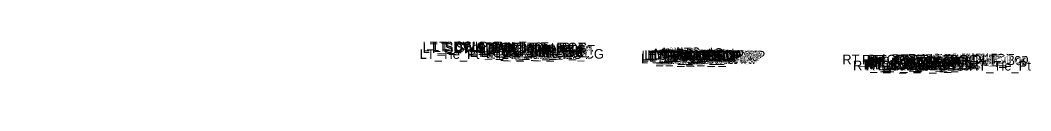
# Model space of a CAD drawing. Extents: x 0 to 4229, y -1 to 9523.
# Drawn here: x 4000 to 4209.1, y 2000 to 2010 of the extents above; entities that cross this region are included whole.
import ezdxf

# ---------------------------------------------------------------- set-up
doc = ezdxf.new("R2010")
doc.units = 0
doc.layers.add('Default', color=7, linetype='Continuous')

msp = doc.modelspace()

# ---------------------------------------------------------------- texts
at = {"layer": 'Default'}
for s, height, p in [('LT_SDWK_Out_Top', 2, (4083.24, 2007.94)), ('LT_CSLP_Pnt', 2, (4085.17, 2007.97)), ('LT_Sub_Trench_Out_DLT', 2, (4085.57, 2007.77)), ('LT_SDWK_In_Top', 2, (4089.86, 2007.84)), ('LT_CG_Top_Face', 2, (4094.76, 2007.73)), ('LT_CG_Top_BOC', 2, (4095.28, 2007.73)), ('LT_Tie_Pt', 2, (4082.66, 2006.38)), ('LT_SDWK_Out_Bot', 2, (4083.27, 2007.61)), ('LT_SDWK_In_Bot', 2, (4089.89, 2007.51)), ('LT_CG1_Shelf_Out', 2, (4093.05, 2006.76)), ('LT_CG_Bot_BOC', 2, (4095.31, 2006.74)), ('LT_CG_Top_Gut', 2, (4095.74, 2007.23)), ('LT_Sub_OEOP', 2, (4096.37, 2006.52)), ('LT_Sub_OEOT_CG', 2, (4096.87, 2006.41)), ('LT_CG_Bot_IE', 2, (4099.41, 2006.66)), ('LT_Sub_OEOT', 2, (4099.58, 2006.37)), ('LT_PV2_OEOT', 2, (4099.67, 2007)), ('LT_PV3_OEOT', 2, (4099.67, 2006.75)), ('LT_PV1_OEOT', 2, (4100.24, 2007.25)), ('LT_PV2_OEEOP', 2, (4128.56, 2006.05)), ('LT_PV3_OEEOP', 2, (4128.56, 2005.8)), ('LT_PV1_OEEOP', 2, (4129.12, 2006.18)), ('LT_PV2_IEEOP', 2, (4129.2, 2006.05)), ('LT_PV1_IEEOP', 2, (4129.77, 2006.18)), ('LT_PV2_PGL1', 2, (4130.13, 2006.05)), ('LT_PV3_PGL1', 2, (4130.13, 2005.8)), ('LT_PV2_PGL', 2, (4130.46, 2006.05)), ('LT_PV1_PGL', 2, (4131.03, 2006.3)), ('MI_Face In', 2, (4131.15, 2006.47)), ('MI_Bot In', 2, (4132.13, 2006.3)), ('RT_PV2_OEEOP', 2, (4132.51, 2005.92)), ('RT_PV3_OEEOP', 2, (4132.51, 2005.67)), ('MI_Top In', 2, (4132.86, 2006.72)), ('RT_PV1_OEEOP', 2, (4133.08, 2006.05)), ('RT_PV2_IEEOP', 2, (4133.16, 2005.92)), ('MI_Face Out', 2, (4133.51, 2006.34)), ('MI_Top Out', 2, (4133.72, 2006.59)), ('RT_PV1_IEEOP', 2, (4133.72, 2006.05)), ('RT_PV2_PGL1', 2, (4134.08, 2005.92)), ('RT_PV3_PGL1', 2, (4134.08, 2005.67)), ('MI_Crown', 2, (4134.32, 2006.74)), ('RT_PV2_PGL', 2, (4134.42, 2005.92)), ('MI_Bot Out', 2, (4134.51, 2006.17)), ('RT_PV1_PGL', 2, (4134.98, 2006.17)), ('LT_Sub_OEEOP', 2, (4128.46, 2005.43)), ('LT_PV4_PGL', 2, (4130.46, 2005.43)), ('RT_Sub_OEEOP', 2, (4132.42, 2005.3)), ('RT_PV4_PGL', 2, (4134.42, 2005.3)), ('RT_Sub_Trench_Out_DLT', 2, (4170.11, 2005.25)), ('RT_Sub_OEOT_CG', 2, (4172.32, 2004.02)), ('RT_CG_Top_Face', 2, (4174.21, 2005.21)), ('RT_CG1_Shelf_Out', 2, (4174.5, 2004.17)), ('RT_CG_Bot_IE', 2, (4174.87, 2004.27)), ('RT_Sub_OEOT', 2, (4175.03, 2003.97)), ('RT_PV2_OEOT', 2, (4175.13, 2004.6)), ('RT_PV3_OEOT', 2, (4175.13, 2004.35)), ('RT_CG_Top_Gut', 2, (4175.19, 2004.71)), ('RT_PV1_OEOT', 2, (4175.69, 2004.85)), ('RT_CG_Top_BOC', 2, (4175.74, 2005.21)), ('RT_CG_Bot_BOC', 2, (4175.77, 2004.19)), ('RT_Sub_OEOP', 2, (4178.32, 2003.91)), ('RT_SDWK_In_Top', 2, (4180.31, 2005.32)), ('RT_SDWK_In_Bot', 2, (4180.34, 2004.98)), ('RT_SDWK_Out_Top', 2, (4183.69, 2005.42)), ('RT_SDWK_Out_Bot', 2, (4183.72, 2005.08)), ('RT_Shld_O', 2, (4190.04, 2005.41)), ('CSLP_Pnt', 2, (4192.37, 2005.45)), ('RT_Tie_Pt', 2, (4196.36, 2003.96)), ('-', 0.0001, (4000, 2000)), ('-', 0.0001, (4000, 2000)), ('-', 0.0001, (4000, 2000)), ('-', 0.0001, (4000, 2000)), ('-', 0.0001, (4000, 2000)), ('-', 0.0001, (4000, 2000)), ('-', 0.0001, (4000, 2000))]:
    msp.add_text(s, height=height, dxfattribs=at).set_placement(p)

doc.saveas('drawing.dxf')
